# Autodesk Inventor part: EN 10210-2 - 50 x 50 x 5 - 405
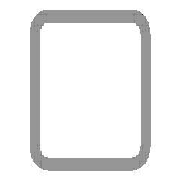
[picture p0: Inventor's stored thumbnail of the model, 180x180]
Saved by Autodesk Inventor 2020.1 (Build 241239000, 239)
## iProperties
_CCFamilyMember: 16
_CCFamilyDisplayName: DIN EN 10210-2 (USAS B17.1 quadratisch) - Rohrleitung — In Klammern angegebene Größen wurden aufgehoben
_FrameMemberDoc: Frame Member File
_Version: 15.0.0
_GetPNFromCC: 1
IsCustomPart: 1
Created: 2019-10
Part Number: EN 10210-2 - 50 x 50 x 5 - 405
Material: Stahl, weich
Description: Rohrleitung
Document SubType Name: Modeling
Standard: DIN
Designer: lutzd
Standard Revision: 2006-07
Standards Organization: DIN
Language: de-DE
Size Designation: 50 x 50 x 5
Categories: <MemberInstance><Categories><Category DisplayName="Profile" InternalName="089c4875-fa83-4c05-b084-43b9cc11f5ed" Mnemonic="GRDR"><CategoryParameter DisplayName="
Stock Number: 50 x 50 x 5
Mass: 2776.04 g
Surface Area: 1388.55 cm^2
Volume: 353.636 cm^3
Density: 7.85 g/cm^3
Appearance: Halbpoliert
G_L: 405,000 mm
G_W: 50,000 mm
G_H: 50,000 mm
Dimensions: 50x50x405 mm
Mass: 2,776 kg
DocNumber: ADSK-014095
Folder: .
+513DCC65-E72F-435E-924B-89ADD4C14BA7+SCHNITTDETAIL1: Schnittwinkel 90,00 grd
Title: Profil-Bauteil
Author: lutzd
Revision Number: -
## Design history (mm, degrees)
node "Startebene"
node "Endebene"
sketch "Skizze"
  geometry: L1 (-25, -17.5)-(-25, 17.5); L2 (-17.5, 25)-(17.5, 25); L3 (25, 17.5)-(25, -17.5); L4 (17.5, -25)-(-17.5, -25); L5 (-15, 20)-(15, 20); L6 (20, 15)-(20, -15); L7 (15, -20)-(-15, -20); L8 (-20, -15)-(-20, 15); L9 (0, 37.175)-(0, -37.175) reference; L10 (-37.175, 0)-(37.175, 0) reference; A1 r 7.5 centre (-17.5, -17.5) between (-25, -17.5) and (-17.5, -25); A2 r 7.5 centre (-17.5, 17.5) between (-17.5, 25) and (-25, 17.5); A3 r 7.5 centre (17.5, 17.5) between (25, 17.5) and (17.5, 25); A4 r 7.5 centre (17.5, -17.5) between (17.5, -25) and (25, -17.5); A5 r 5 centre (-15, -15) between (-20, -15) and (-15, -20); A6 r 5 centre (-15, 15) between (-15, 20) and (-20, 15); A7 r 5 centre (15, 15) between (20, 15) and (15, 20); A8 r 5 centre (15, -15) between (15, -20) and (20, -15)
  constraints: 16 end point, 16 point on circle, 16 tangent, 8 centre point, 6 equal radius, 4 parallel, 2 perpendicular, 2 other
  dimensions: "d7" = 7.5 radius of A1 (= G_IR); "d10" = 50 distance between parallel lines of L2 L4 (= G_H); "d11" = 50 distance between parallel lines of L1 L3 (= G_W); "d12" = 5 distance between parallel lines of L3 L6 (= G_T); "d15" = 25 distance between parallel lines of L2 L10 (= 0.5 x d10); "d16" = 25 distance between parallel lines of L9 L3 (= 0.5 x d11); "d19" = 5 radius of A5 (= G_T); "d20" = 5 distance between parallel lines of L4 L7 (= G_T)
extrude "Körper" new body sketch "Skizze" stored distance "d3" = 405 (= G_L); taper "d4" = 0 deg
node "Driven Length"
  sketch "Sketch3"
    geometry: L1 (0, 0)-(10, 0) reference
    constraints: 2 end point, 1 horizontal
  workplane "Work Plane3"
  sketch "Sketch4"
    geometry: L1 (-2, 0)-(12, 0) reference; L2 (-2, 405)-(12, 405) reference
    dimensions: "d18" = 405 distance between parallel lines of L1 L2 (derived)
workplane "Arbeitsebene4"
feature "Trennen1"
body "Solid1"
other parameters: "G_W" = 50 [user parameter; used in 1 equation term], "G_H" = 50 [user parameter; used in 1 equation term], "G_T" = 5 [user parameter; used in 3 equation terms], "G_IR" = 7.5 [user parameter; used in 1 equation term], "G_L" = 405 (= d18) [user parameter; used in 1 equation term], "G_OFFSET_START" = 0 [user parameter; used in 1 equation term], "d13" = 0 (computed from G_OFFSET_START), "d14" = 405 (= G_OFFSET_END + B_L), "B_L" = 455 [user parameter; used in 1 equation term], "d17" = 90 deg
